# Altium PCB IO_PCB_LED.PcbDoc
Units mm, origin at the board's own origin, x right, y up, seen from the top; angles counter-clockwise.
Board outline 25.4 x 22.86 mm, 2 copper layers (Top Layer, Bottom Layer); 13 components, 11 nets, 44 pads, 1 vias.
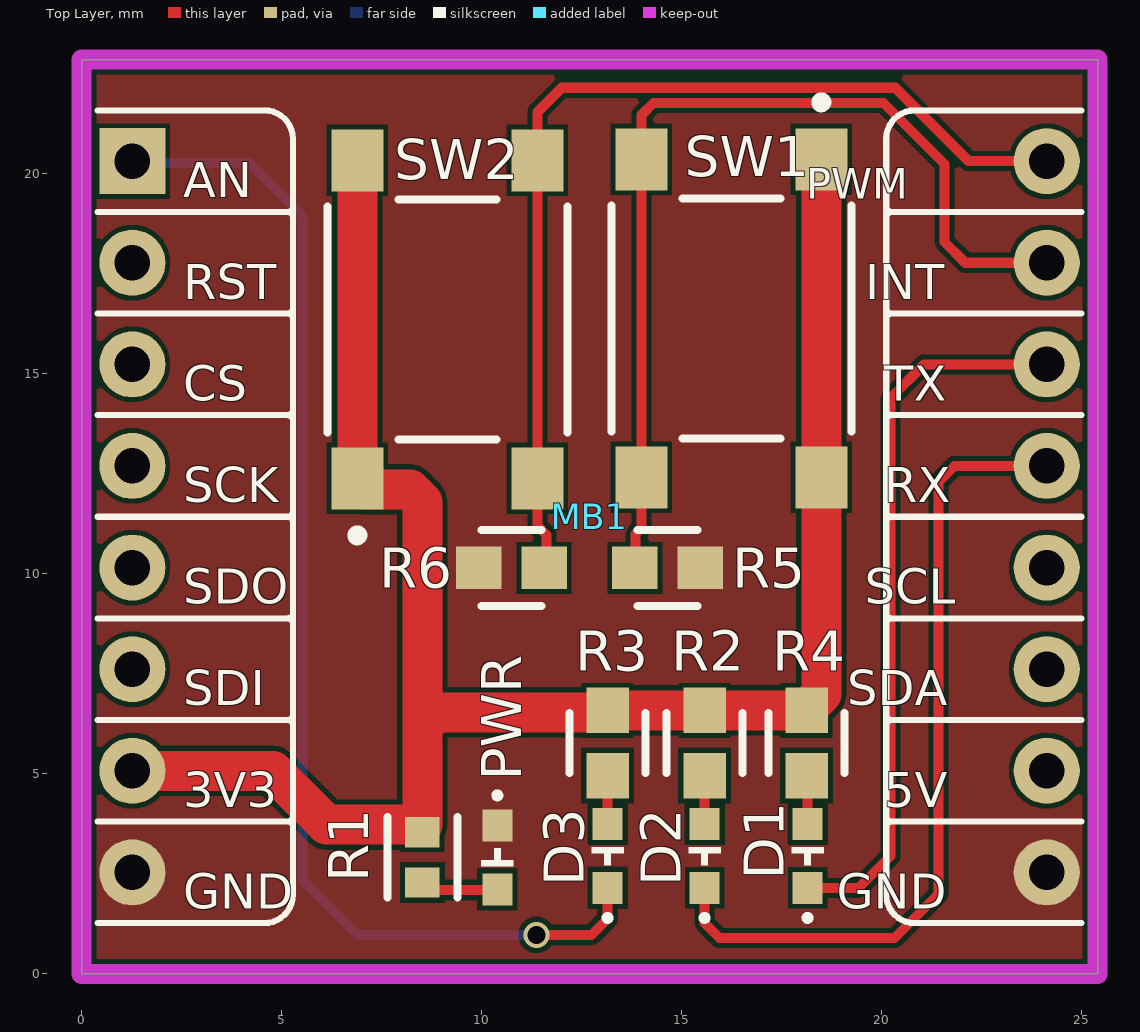
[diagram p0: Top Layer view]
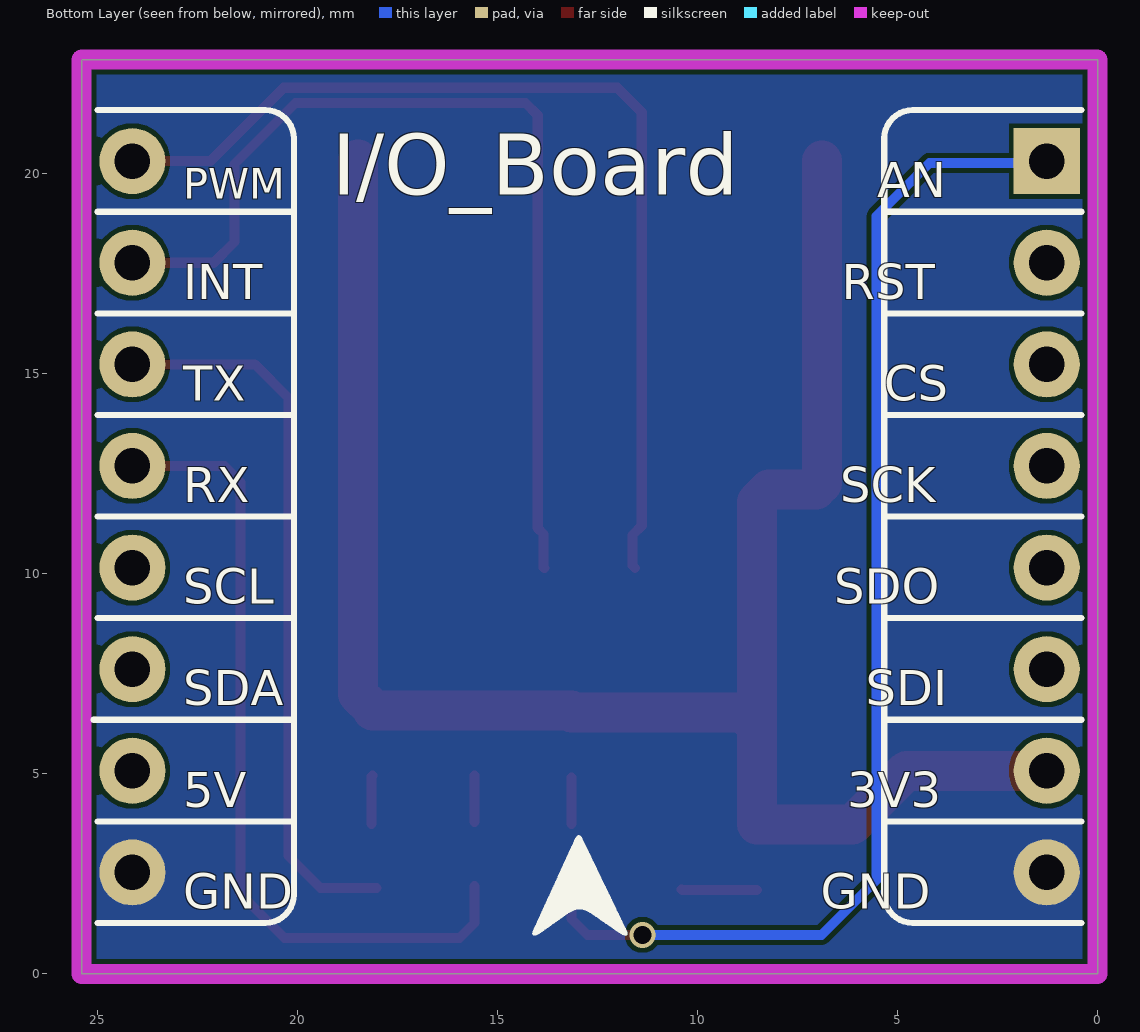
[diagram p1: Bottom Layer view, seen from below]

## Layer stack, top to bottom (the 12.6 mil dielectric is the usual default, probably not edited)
Top Solder: solder mask 0.0102, Solder Resist, Dk 3.5
Top Layer: signal copper 0.0356
Dielectric 1: dielectric 0.32, FR-4, Dk 4.8
Bottom Layer: signal copper 0.0356
Bottom Solder: solder mask 0.0102, Solder Resist, Dk 3.5

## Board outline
0,0 0,22.86 25.4,22.86 25.4,0

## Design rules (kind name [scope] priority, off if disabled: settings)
Clearance [All] p1: gap=0.125 ignorepadtopadclearanceinfootprint=FALSE
HoleSize HoleSizeVia [IsVia] p1: absolutevalues=TRUE maxlimit=0.45 minlimit=0.25 maxpercent=80.000 minpercent=20.000
HoleSize HoleSizePTH [IsPad] p2: absolutevalues=TRUE maxlimit=5.6 minlimit=0.5 maxpercent=80.000 minpercent=20.000
HoleToHoleClearance [All] p1: gap=0.3 allowstackedmicrovias=TRUE
MinimumAnnularRing MinimumAnnularRingVias [All] p1: minimumring=0.1
MinimumAnnularRing MinimumAnnularRingGeneral [All] p2: minimumring=0.3
MinimumSolderMaskSliver [All] p1: minsoldermaskwidth=0.08
PasteMaskExpansion [All] p1: expansion=0.085
PolygonConnect [All] p1: connectstyle=Direct reliefconductorwidth=0.254 reliefentries=4 polygonreliefangle="90 Angle" airgapwidth=0.254
RoutingVias [All] p1: holewidth=0.35 width=0.55 viastyle="Through Hole" minholewidth=0.3 minwidth=0.5 maxholewidth=0.45 maxwidth=0.65
SilkToSilkClearance SilkToSilkClerance [All] p1: silktosilkclearance=0.125
SilkToSolderMaskClearance [IsPad] p1: minsilkscreentomaskgap=0.125 clearancetoexposedcopper=TRUE
SolderMaskExpansion SolderMaskExpansionVia [IsVia] p1: expansion=0.1 istentingtop=TRUE useseparateexpansions=TRUE expansionbottom=0.1 istentingbottom=TRUE
SolderMaskExpansion [All] p2: expansion=0.075 istentingtop=FALSE
SupplyNets "Schematic Supply Nets_2" [InNet('+3V3')] p1: voltage=0.000
SupplyNets "Schematic Supply Nets_1" [InNet('GND')] p2: voltage=0.000
UnRoutedNet [All] p1: checkbadconnections=TRUE
Width [All] p1: maxlimit=2.54 minlimit=0.125 preferedwidth=0.254
23 further rules are at their usual default settings.

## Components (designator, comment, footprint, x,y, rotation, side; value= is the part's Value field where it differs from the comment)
D1 "150060GS55040" WL-SMCD_0603 -1251.85,1272.95 r90 top
D2 "150060BS55040" WL-SMCD_0603 -1254.425,1272.95 r90 top
D3 "150060RS55040" WL-SMCD_0603 -1256.85,1272.95 r90 top
MB1 "Embedd_Sensor_Schields" "Embedd_add_on_board_25,4 x 22,86" 0,0 r0 top
PWR "150060GS55040" WL-SMCD_0603 1280.395,-1267.085 r270 top
R1 "300" FP-CRCW0603-HPe3-IPC_C 8.52,2.915 r90 top
R2 "43" FP-CRCW0603-e3-IPC_A 15.575,5.775 r90 top
R3 "56" FP-CRCW0603-e3-IPC_A 13.15,5.775 r90 top
R4 "56" FP-CRCW0603-e3-IPC_A 18.125,5.775 r90 top
R5 "10k" FP-CRCW0603-e3-IPC_A 14.65,10.15 r180 top
R6 "10k" FP-CRCW0603-e3-IPC_A 10.75,10.15 r0 top
SW1 "PTS645SM43SMTR92LFS" FP-PTS645SM43SMTR92LFS-MFG 16.245,16.39 r270 top
SW2 "PTS645SM43SMTR92LFS" FP-PTS645SM43SMTR92LFS-MFG 9.145,16.365 r90 top

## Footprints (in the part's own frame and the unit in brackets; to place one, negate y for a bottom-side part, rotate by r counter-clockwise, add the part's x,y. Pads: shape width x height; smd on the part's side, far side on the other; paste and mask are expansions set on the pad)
"Embedd_add_on_board_25,4 x 22,86" [mil] "Small footprint"
  rect 65x65 hole 35: 1(50,800)
  round 65 hole 35: 2(50,700) 3(50,600) 4(50,500) 5(50,400) 6(50,300) 7(50,200) 8(50,100) 9(950,100) 10(950,200) 11(950,300) 12(950,400) 13(950,500) 14(950,600) 15(950,700) 16(950,800)
  silkscreen extent 16,50 984,850, body extent 0,51 1000,851, height 103
FP-CRCW0603-e3-IPC_A [mm]
  rect 1.135x1.062 smd paste+0 mask+0: 1(-0.815,0) 2(0.815,0)
  silkscreen extent -0.75,-0.95 0.75,0.95, body extent -1.88,-1.03 1.88,1.03, height 0.25
FP-CRCW0603-HPe3-IPC_C [mm]
  rect 0.758x0.862 smd paste+0 mask+0: 1(-0.627,0) 2(0.627,0)
  silkscreen extent -1.01,-0.87 1.01,0.87, body extent -1.11,-0.58 1.11,0.58, height 0.25
FP-PTS645SM43SMTR92LFS-MFG [mm]
  rect 1.55x1.3 smd paste+0 mask+0: 1(-3.975,2.25) 2(3.975,2.25) 3(-3.975,-2.25) 4(3.975,-2.25)
  silkscreen extent -5.52,-3 3,3, body extent -4.85,-3.1 4.85,3.1, height 0.25
WL-SMCD_0603 [mm] "SMD Mono-color Chip LED, body 1.6x0.8mm"
  rect 0.8x0.75 smd: 1(-1270.8,-1270) 2(-1269.2,-1270)
  silkscreen extent -1271.62,-1270.4 -1269.78,-1269.6, body extent -1270.8,-1270.4 -1269.2,-1269.6, height 0.42

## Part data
D1 PWR: library part CMP-03913-90235563-2, "150060GS55040 WL-SMCD SMT Mono-color Chip LED Diffused", Forward Current=60mA, Forward Voltage=3.2V, Max Operating Temperature=85°C, Max Reverse Voltage (DC)=5V, Min Operating Temperature=-40°C
D2: library part CMP-03913-90235561-2, "150060BS55040 WL-SMCD SMT Mono-color Chip LED Diffused", Forward Current=60mA, Forward Voltage=3.2V, Max Operating Temperature=85°C, Max Reverse Voltage (DC)=5V, Min Operating Temperature=-40°C
D3: library part CMP-207942-000007-3, "LED RED DIFFUSED 0603 SMD", Case/Package=0603, Color=Red, Forward Current=40mA, Forward Voltage=2V, Max Junction Temperature (Tj)=115°C, Max Operating Temperature=85°C, Max Reverse Voltage (DC)=5V, Min Operating Temperature=-40°C, Power Dissipation=48mW
MB1: library part CMP-00030-00005-3, "Footprint for sensor shields", Max Operating Temperature=85°C, Min Operating Temperature=-40°C
R1: library part CMP-02407-005270-1, "RES Thick Film, 300Ω, 1%, 0.33W, 100ppm/°C, 0603", Case Code (Imperial)=0603, Case Code (Metric)=1608, Max Operating Temperature=155°C, Max Power Dissipation=250mW, Min Operating Temperature=-55°C, Package Quantity=5000, Resistance=300R, Temperature Coefficient=100ppm/°C, Tolerance=1%, Voltage Rating=75V
R2 R3 R4 R5 R6: library part CMP-2000-03250-2, "RES Thick Film, 33Ω, 1%, 0.1W, 100ppm/°C, 0603", Case Code (Imperial)=0603, Case Code (Metric)=1608, Max Operating Temperature=155°C, Max Power Dissipation=100mW, Min Operating Temperature=-55°C, Package Quantity=10, Resistance=33R, Temperature Coefficient=100ppm/°C, Tolerance=1%, Voltage Rating=75V
SW1 SW2: library part CMP-2000-05160-2, "SWITCH TACTILE SPST-NO 0.05A 12V", Case/Package=SMD/SMT, Color=Black, Contact Resistance=100mR, Current Rating=50mA, Max Operating Temperature=60°C, Max Voltage Rating (DC)=12V, Min Operating Temperature=-20°C, Operating Force=160gf, Package Quantity=1

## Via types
v1: diameter 0.65, hole 0.45, Top Layer to Bottom Layer, tented both sides, 1 vias

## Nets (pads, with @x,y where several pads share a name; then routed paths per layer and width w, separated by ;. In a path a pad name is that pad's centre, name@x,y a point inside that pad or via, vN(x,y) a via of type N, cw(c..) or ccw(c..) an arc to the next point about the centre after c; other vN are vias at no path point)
+3V3: MB1.7 R1.2 R2.2 R3.2 R4.2 SW1.1 SW1.2 SW2.1 SW2.2 | length 49.5
  Top Layer w1: MB1.7 4.78,5.08 6.13,3.73 8.52,3.73 8.52,6.187 ; SW2.2 SW2.1 6.895,12.265 7.045,12.115 8.209,12.115 8.52,11.804 8.52,6.187 ; R3.2@13.15,6.54 8.873,6.54 8.52,6.187 ; R3.2 R2.2 R4.2 18.125,6.627 18.495,6.997 SW1.1
GND: MB1.8 MB1.9 PWR.1 R5.1 R6.1
LED_B: D2.1 MB1.13 | length 20.6
  Top Layer w0.254: D2.1@15.575,2.2 15.575,1.275 15.95,0.9 20.325,0.9 21.425,2 21.425,12.3 21.825,12.7 MB1.13
LED_G: D1.1 MB1.14 | length 18.2
  Top Layer w0.254: D1.1@18.025,2.15 19.425,2.15 20.225,2.95 20.225,14.4 21.065,15.24 MB1.14
LED_R: D3.1 MB1.1 | length 30.6
  Top Layer w0.254: v1(11.375,0.975) 12.75,0.975 13.15,1.375 D3.1
  Bottom Layer w0.254: MB1.1 1.315,20.275 4.2,20.275 5.525,18.95 5.525,2.35 6.9,0.975 v1(11.375,0.975)
NetD1_2: D1.2 R4.1 | length 1.2
  Top Layer w0.254: R4.1 18.15,4.935 D1.2
NetD2_2: D2.2 R2.1 | length 1.2
  Top Layer w0.254: D2.2@15.575,3.8 R2.1
NetD3_2: D3.2 R3.1 | length 1.2
  Top Layer w0.254: D3.2 R3.1@13.15,4.91
NetPWR_2: PWR.2 R1.1 | length 1.9
  Top Layer w0.254: R1.1@8.52,2.1 10.38,2.1 PWR.2
SW_1: MB1.15 R5.2 SW1.3 SW1.4 | length 24.4
  Top Layer w0.254: R5.2 13.85,10.165 13.85,11 13.995,11.145 SW1.4 13.995,21.47 14.3,21.775 20.05,21.775 21.575,20.25 21.575,18.3 22.095,17.78 MB1.15
SW_2: MB1.16 R6.2 SW2.3 SW2.4 | length 25.3
  Top Layer w0.254: R6.2 11.625,10.21 11.625,10.975 11.395,11.205 SW2.3 SW2.4 11.395,21.545 12.004,22.154 20.346,22.154 22.18,20.32 MB1.16
pads on no net: MB1.2 MB1.3 MB1.4 MB1.5 MB1.6 MB1.10 MB1.11 MB1.12

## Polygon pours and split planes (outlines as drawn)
GND on Top Layer "NONET_L-01_P-001" (solid, pour order 0): 0,22.84 0,0.015 25.375,0.015 25.375,22.84
GND on Bottom Layer "NONET_L-01_P-001" (solid, pour order 1): -0.005,22.815 -0.005,-0.01 25.37,-0.01 25.37,22.815

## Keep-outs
Keep-Out Layer:
  the board outline again, w0.5

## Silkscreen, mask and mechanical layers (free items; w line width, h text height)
Bottom Overlay:
  text "I/O_Board" at 19.146,19.483 h1.52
